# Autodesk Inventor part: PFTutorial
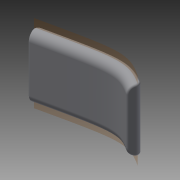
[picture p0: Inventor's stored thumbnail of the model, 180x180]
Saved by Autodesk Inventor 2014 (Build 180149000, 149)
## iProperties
Created: 2008-04
Part Number: PFTutorial
Document SubType Name: Modeling
Designer: gpbassi
Density: 1 g/cm^3
Material: Generic
Appearance: Default
Author: gpbassi
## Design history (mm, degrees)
sketch "SpineSketch"
  geometry: 4 further points
  constraints: 4 other
node "GrillWorkPlane"
node "RestWorkPlane"
node "BossWorkPlane1"
sketch "BossSketch1"
  geometry: 2 further points
node "BossWorkPlane2"
sketch "BossSketch2"
  geometry: 2 further points
sketch "Revolve_NewBody"
  geometry: L1 (-11.76, 31.812)-(-11.76, 29.5); L2 (-11.76, 29.5)-(-7.25, 29.5); L3 (-7.25, 29.5)-(-7.25, 28.5); L4 (-7.25, 28.5)-(-11.76, 28.5); L5 (-11.76, 28.5)-(-11.76, 25.75); L6 (-11.76, 25.75)-(-8, 25.75); L7 (-8, 25.75)-(-8, 17.5); L8 (-8, 17.5)-(0, 17.5); L9 (0, 17.5)-(0, 0); L10 (0, 37.5)-(0, 17.5); A1 r 15 centre (0, 22.5) between (0, 37.5) and (-11.76, 31.812); 2 further points
  constraints: 20 end point, 5 parallel, 3 collinear, 2 coincident, 2 perpendicular, 2 point on circle, 1 centre point, 1 horizontal, 1 point on line
  dimensions: "d121" = 15 radius of A1; "d122" = 20 distance of L10.start L8.end; "d123" = 8 distance of L7.end L8.end; "d124" = 17.5 distance from line of L8 point (0, 0); "d125" = 7.25 distance between parallel lines of L3 L10; "d126" = 11.75984 distance between parallel lines of L1 L10; "d127" = 8.25 distance between parallel lines of L6 L8; "d128" = 12 distance between parallel lines of L2 L8; "d129" = 11 distance between parallel lines of L4 L8
node "SectionWorkPlane"
sketch "SectionSketch"
  geometry: L1 (17, 0)-(-19, 0) reference; L2 (0, -51)-(0, 53) reference; L3 (-14, -39.559)-(-14, 39.559); L4 (5, 52.635)-(5, -52.635); A1 r 14 centre (0, -39.559) between (-14, -39.559) and (5, -52.635); A2 r 14 centre (0, 39.559) between (5, 52.635) and (-14, 39.559); 2 further points
  constraints: 8 end point, 5 point on circle, 3 point on line, 3 symmetric about line, 2 centre point, 1 horizontal, 1 parallel, 1 perpendicular, 1 tangent, 1 vertical, 1 other
  dimensions: "d96" = 19 distance between parallel lines of L3 L4; "d97" = 5 distance between parallel lines of L4 L2
sweep "Sweep1" sketch "SectionSketch" dims "d62" = 0
extrude_surface "PartingSurface" dims "d63" = 134, "d64" = 0
sketch "GrillSketch"
  geometry: L1 (-59.25, -36.361)-(-59.25, 36.361); L2 (-100.75, 36.361)-(-100.75, -36.361); L3 (-62, -50)-(-62, 50); L4 (-66, -50)-(-66, 50); L5 (-70, -50)-(-70, 50); L6 (-74, -50)-(-74, 50); L7 (-78, -50)-(-78, 50); L8 (-82, -50)-(-82, 50); L9 (-86, -50)-(-86, 50); L10 (-90, -50)-(-90, 50); L11 (-94, -50)-(-94, 50); L12 (-98, -50)-(-98, 50); L13 (-102, 0)-(-57, 0) reference; L14 (-80, -47)-(-80, 47) reference; A1 r 32 centre (-80, -12) between (-100.75, -36.361) and (-59.25, -36.361); A2 r 32 centre (-80, 12) between (-59.25, 36.361) and (-100.75, 36.361); A3 r 32 centre (-80, 12) between (-106.819, -5.457) and (-52.691, -4.68); A4 r 32 centre (-80, -12) between (-52.691, 4.68) and (-106.819, 5.457)
  constraints: 28 end point, 8 point on circle, 4 centre point, 3 parallel, 3 symmetric about line, 1 coincident, 1 horizontal, 1 perpendicular, 1 vertical, 4 other
  dimensions: "d82" = 32 radius of A1; "d83" = 20.75 distance between parallel lines of L2 L14; "d84" = 32 radius of A2; "d85" = 32 radius of A3
sketch "RestSketch"
  geometry: L1 (34, 0)-(-25, 0); L2 (34, 0)-(-25, 0); L3 (-7.849, 32.548)-(-13.735, 2.71); L4 (-8, -31)-(-8, -11.489); L5 (7.849, -32.548)-(13.735, -2.71); L6 (8, 31)-(8, 11.489); A1 r 8 centre (0, -31) between (-8, -31) and (7.849, -32.548); A2 r 8 centre (0, 31) between (8, 31) and (-7.849, 32.548); A3 r 14 centre (0, 0) between (13.735, -2.71) and (8, 11.489); A4 r 14 centre (0, 0) between (-13.735, 2.71) and (-8, -11.489)
  constraints: 12 end point, 8 point on circle, 6 tangent, 4 centre point, 2 horizontal, 1 parallel, 1 perpendicular, 1 point on line
feature "BatterySplitSurface" dims "d120" = 0.254 (derived)
workpoint "Work Point3"
workpoint "Work Point4"
body "Solid1"
fillet "Fillet1" dims "d98" = 8
fillet "Fillet2" dims "d99" = 3
workpoint "Work Point1"
workpoint "Work Point2"
body "Srf1"
sketch "BatterySketch"
  geometry: L1 (-10.134, -25)-(-18, -25); L2 (-18, -25)-(-18, 25); L3 (-18, 25)-(-10.134, 25); L4 (-9.134, 24)-(-9.134, -24); L5 (2, 0)-(-25, 0) reference; A1 r 1 centre (-10.134, -24) between (-10.134, -25) and (-9.134, -24); A2 r 1 centre (-10.134, 24) between (-9.134, 24) and (-10.134, 25)
  constraints: 10 end point, 4 point on circle, 4 tangent, 2 centre point, 2 horizontal, 2 parallel, 2 perpendicular, 1 equal radius, 1 other
  dimensions: "d104" = 1 radius of A1
body "Srf3"
body "Srf4"
body "Srf2"
extrude_surface "ExtrusionSrf3" dims "d105" = 36, "d106" = 0
patch "Boundary Patch1" dims "d107" = 0, "d108" = 0, "d109" = 0
other parameters: "d102" = 24, "d110" = 4.5, "d115" = 11.75
